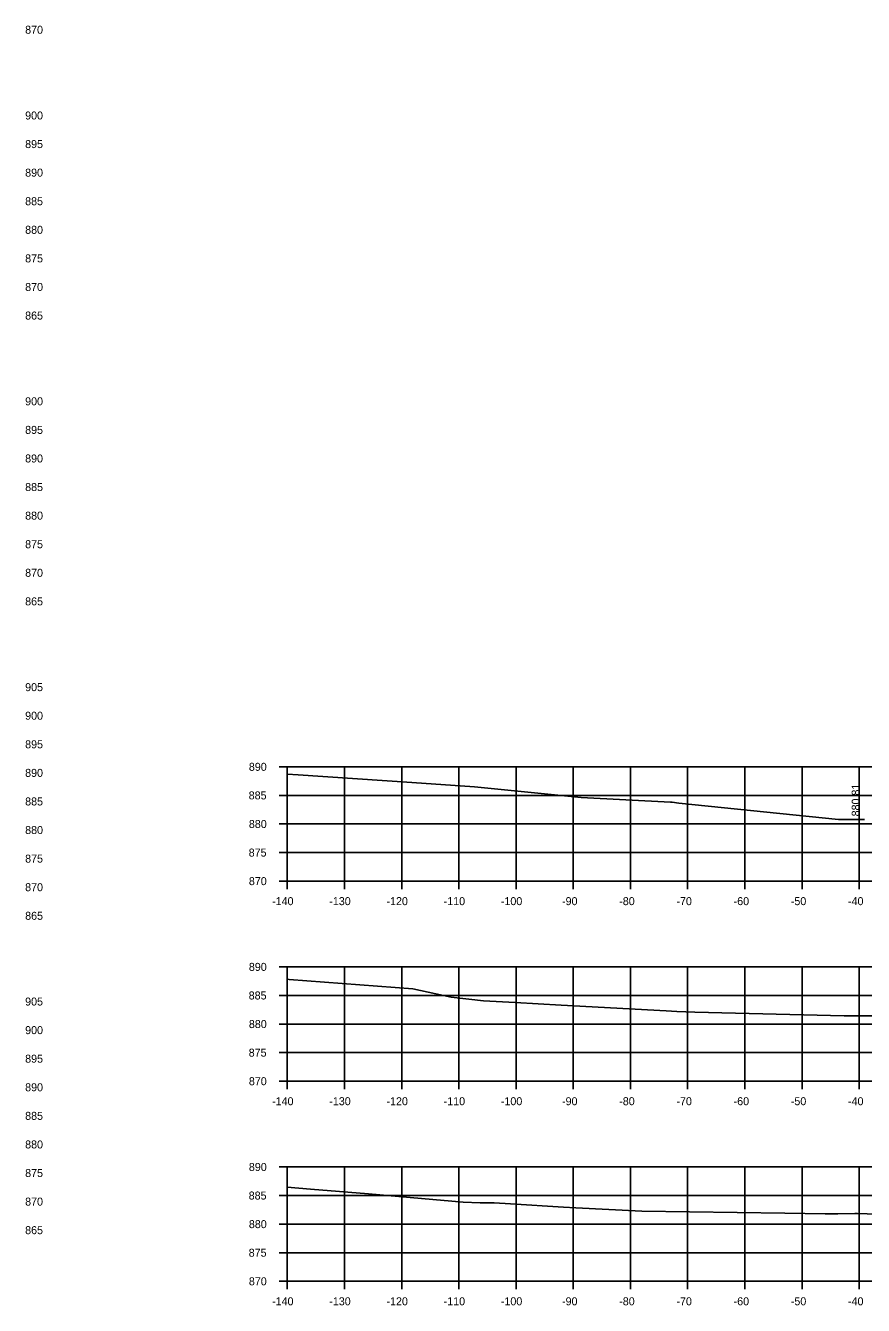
# Model space of a CAD drawing. Extents: x 1098669 to 1198896, y 698679 to 704410.
# Drawn here: x 1112452.1 to 1112598.6, y 701462.1 to 701686 of the extents above; entities that cross this region are included whole.
import ezdxf

# ---------------------------------------------------------------- set-up
doc = ezdxf.new("R2010")
doc.units = 0
for name, color, linetype in [('59', 7, 'Continuous'), ('Proposed Surface', 7, 'Continuous'), ('R_Axis', 7, 'Continuous'), ('R_Axis Annot', 7, 'Continuous'), ('R_Grid', 7, 'Continuous')]:
    doc.layers.add(name, color=color, linetype=linetype)

msp = doc.modelspace()

# ---------------------------------------------------------------- linework, layer by layer
at = {"layer": 'Proposed Surface'}
for points in [[(1112497.82, 701555.06), (1112499.72, 701554.92), (1112519.61, 701553.58), (1112530.55, 701552.84), (1112549.19, 701550.96), (1112564.83, 701550.12), (1112565.09, 701550.11), (1112566.26, 701549.97), (1112594.18, 701547.11), (1112597.47, 701547.11), (1112598.76, 701547.13)], [(1112497.82, 701519.15), (1112498.15, 701519.13), (1112519.79, 701517.47), (1112526.5, 701516), (1112532.12, 701515.4), (1112537.64, 701515.1), (1112545.73, 701514.64), (1112564.06, 701513.62), (1112565.92, 701513.52), (1112569.05, 701513.42), (1112595.2, 701512.74), (1112597.77, 701512.73), (1112600.14, 701512.76)], [(1112497.82, 701482.79), (1112501.88, 701482.44), (1112511.99, 701481.63), (1112528.56, 701480.15), (1112531.52, 701480.04), (1112533.98, 701480.03), (1112536.83, 701479.86), (1112546.1, 701479.31), (1112548.25, 701479.18), (1112559.8, 701478.6), (1112584.8, 701478.21), (1112591.85, 701478.11), (1112592.09, 701478.11), (1112594.1, 701478.14), (1112597.05, 701478.17), (1112597.52, 701478.16), (1112602.56, 701478.01)]]:
    msp.add_lwpolyline(points, dxfattribs=at)
at = {"layer": 'R_Axis'}
for p, q in [((1112496.42, 701556.32), (1112497.82, 701556.32)), ((1112497.82, 701536.32), (1112497.82, 701556.32)), ((1112496.42, 701551.32), (1112497.82, 701551.32)), ((1112496.42, 701546.32), (1112497.82, 701546.32)), ((1112496.42, 701541.32), (1112497.82, 701541.32)), ((1112496.42, 701536.32), (1112497.82, 701536.32)), ((1112497.82, 701536.32), (1112777.82, 701536.32)), ((1112497.82, 701534.92), (1112497.82, 701536.32)), ((1112507.82, 701534.92), (1112507.82, 701536.32)), ((1112517.82, 701534.92), (1112517.82, 701536.32)), ((1112527.82, 701534.92), (1112527.82, 701536.32)), ((1112537.82, 701534.92), (1112537.82, 701536.32)), ((1112547.82, 701534.92), (1112547.82, 701536.32)), ((1112557.82, 701534.92), (1112557.82, 701536.32)), ((1112567.82, 701534.92), (1112567.82, 701536.32)), ((1112577.82, 701534.92), (1112577.82, 701536.32)), ((1112587.82, 701534.92), (1112587.82, 701536.32)), ((1112597.82, 701534.92), (1112597.82, 701536.32)), ((1112496.42, 701521.32), (1112497.82, 701521.32)), ((1112497.82, 701501.32), (1112497.82, 701521.32)), ((1112496.42, 701516.32), (1112497.82, 701516.32)), ((1112496.42, 701511.32), (1112497.82, 701511.32)), ((1112496.42, 701506.32), (1112497.82, 701506.32)), ((1112496.42, 701501.32), (1112497.82, 701501.32)), ((1112497.82, 701501.32), (1112777.82, 701501.32)), ((1112497.82, 701499.92), (1112497.82, 701501.32)), ((1112507.82, 701499.92), (1112507.82, 701501.32)), ((1112517.82, 701499.92), (1112517.82, 701501.32)), ((1112527.82, 701499.92), (1112527.82, 701501.32)), ((1112537.82, 701499.92), (1112537.82, 701501.32)), ((1112547.82, 701499.92), (1112547.82, 701501.32)), ((1112557.82, 701499.92), (1112557.82, 701501.32)), ((1112567.82, 701499.92), (1112567.82, 701501.32)), ((1112577.82, 701499.92), (1112577.82, 701501.32)), ((1112587.82, 701499.92), (1112587.82, 701501.32)), ((1112597.82, 701499.92), (1112597.82, 701501.32)), ((1112496.42, 701486.32), (1112497.82, 701486.32)), ((1112497.82, 701466.32), (1112497.82, 701486.32)), ((1112496.42, 701481.32), (1112497.82, 701481.32)), ((1112496.42, 701476.32), (1112497.82, 701476.32)), ((1112496.42, 701471.32), (1112497.82, 701471.32)), ((1112496.42, 701466.32), (1112497.82, 701466.32)), ((1112497.82, 701466.32), (1112777.82, 701466.32)), ((1112497.82, 701464.92), (1112497.82, 701466.32)), ((1112507.82, 701464.92), (1112507.82, 701466.32)), ((1112517.82, 701464.92), (1112517.82, 701466.32)), ((1112527.82, 701464.92), (1112527.82, 701466.32)), ((1112537.82, 701464.92), (1112537.82, 701466.32)), ((1112547.82, 701464.92), (1112547.82, 701466.32)), ((1112557.82, 701464.92), (1112557.82, 701466.32)), ((1112567.82, 701464.92), (1112567.82, 701466.32)), ((1112577.82, 701464.92), (1112577.82, 701466.32)), ((1112587.82, 701464.92), (1112587.82, 701466.32)), ((1112597.82, 701464.92), (1112597.82, 701466.32))]:
    msp.add_line(p, q, dxfattribs=at)
at = {"layer": 'R_Grid'}
for p, q in [((1112497.82, 701556.32), (1112777.82, 701556.32)), ((1112497.82, 701536.32), (1112497.82, 701556.32)), ((1112507.82, 701536.32), (1112507.82, 701556.32)), ((1112517.82, 701536.32), (1112517.82, 701556.32)), ((1112527.82, 701536.32), (1112527.82, 701556.32)), ((1112537.82, 701536.32), (1112537.82, 701556.32)), ((1112547.82, 701536.32), (1112547.82, 701556.32)), ((1112557.82, 701536.32), (1112557.82, 701556.32)), ((1112567.82, 701536.32), (1112567.82, 701556.32)), ((1112577.82, 701536.32), (1112577.82, 701556.32)), ((1112587.82, 701536.32), (1112587.82, 701556.32)), ((1112597.82, 701536.32), (1112597.82, 701556.32)), ((1112497.82, 701551.32), (1112777.82, 701551.32)), ((1112497.82, 701546.32), (1112777.82, 701546.32)), ((1112497.82, 701541.32), (1112777.82, 701541.32)), ((1112497.82, 701536.32), (1112777.82, 701536.32)), ((1112497.82, 701521.32), (1112777.82, 701521.32)), ((1112497.82, 701501.32), (1112497.82, 701521.32)), ((1112507.82, 701501.32), (1112507.82, 701521.32)), ((1112517.82, 701501.32), (1112517.82, 701521.32)), ((1112527.82, 701501.32), (1112527.82, 701521.32)), ((1112537.82, 701501.32), (1112537.82, 701521.32)), ((1112547.82, 701501.32), (1112547.82, 701521.32)), ((1112557.82, 701501.32), (1112557.82, 701521.32)), ((1112567.82, 701501.32), (1112567.82, 701521.32)), ((1112577.82, 701501.32), (1112577.82, 701521.32)), ((1112587.82, 701501.32), (1112587.82, 701521.32)), ((1112597.82, 701501.32), (1112597.82, 701521.32)), ((1112497.82, 701516.32), (1112777.82, 701516.32)), ((1112497.82, 701511.32), (1112777.82, 701511.32)), ((1112497.82, 701506.32), (1112777.82, 701506.32)), ((1112497.82, 701501.32), (1112777.82, 701501.32)), ((1112497.82, 701486.32), (1112777.82, 701486.32)), ((1112497.82, 701466.32), (1112497.82, 701486.32)), ((1112507.82, 701466.32), (1112507.82, 701486.32)), ((1112517.82, 701466.32), (1112517.82, 701486.32)), ((1112527.82, 701466.32), (1112527.82, 701486.32)), ((1112537.82, 701466.32), (1112537.82, 701486.32)), ((1112547.82, 701466.32), (1112547.82, 701486.32)), ((1112557.82, 701466.32), (1112557.82, 701486.32)), ((1112567.82, 701466.32), (1112567.82, 701486.32)), ((1112577.82, 701466.32), (1112577.82, 701486.32)), ((1112587.82, 701466.32), (1112587.82, 701486.32)), ((1112597.82, 701466.32), (1112597.82, 701486.32)), ((1112497.82, 701481.32), (1112777.82, 701481.32)), ((1112497.82, 701476.32), (1112777.82, 701476.32)), ((1112497.82, 701471.32), (1112777.82, 701471.32)), ((1112497.82, 701466.32), (1112777.82, 701466.32))]:
    msp.add_line(p, q, dxfattribs=at)

# ---------------------------------------------------------------- texts
at = {"layer": '59'}
msp.add_text(' 880.81', height=1.4, rotation=90, dxfattribs=at).set_placement((1112597.91, 701547.13))
at = {"layer": 'R_Axis Annot'}
for s, p in [('870', (1112451.98, 701684.56)), ('900', (1112451.98, 701669.56)), ('895', (1112451.98, 701664.56)), ('890', (1112451.98, 701659.56)), ('885', (1112451.98, 701654.56)), ('880', (1112451.98, 701649.56)), ('875', (1112451.98, 701644.56)), ('870', (1112451.98, 701639.56)), ('865', (1112451.98, 701634.56)), ('900', (1112451.98, 701619.56)), ('895', (1112451.98, 701614.56)), ('890', (1112451.98, 701609.56)), ('885', (1112451.98, 701604.56)), ('880', (1112451.98, 701599.56)), ('875', (1112451.98, 701594.56)), ('870', (1112451.98, 701589.56)), ('865', (1112451.98, 701584.56)), ('905', (1112451.98, 701569.56)), ('900', (1112451.98, 701564.56)), ('895', (1112451.98, 701559.56)), ('890', (1112451.98, 701554.56)), ('890', (1112491.1, 701555.62)), ('885', (1112491.07, 701550.62)), ('885', (1112451.98, 701549.56)), ('880', (1112491.1, 701545.62)), ('880', (1112451.98, 701544.56)), ('875', (1112451.98, 701539.56)), ('875', (1112491.07, 701540.62)), ('870', (1112451.98, 701534.56)), ('870', (1112491.1, 701535.62)), ('-140', (1112495.16, 701532.12)), ('-130', (1112505.16, 701532.12)), ('-120', (1112515.16, 701532.12)), ('-110', (1112525.16, 701532.12)), ('-100', (1112535.16, 701532.12)), ('-90', (1112545.86, 701532.12)), ('-80', (1112555.86, 701532.12)), ('-70', (1112565.86, 701532.12)), ('-60', (1112575.86, 701532.12)), ('-50', (1112585.86, 701532.12)), ('-40', (1112595.86, 701532.12)), ('865', (1112451.98, 701529.56)), ('890', (1112491.1, 701520.62)), ('905', (1112451.98, 701514.56)), ('885', (1112491.07, 701515.62)), ('900', (1112451.98, 701509.56)), ('880', (1112491.1, 701510.62)), ('875', (1112491.07, 701505.62)), ('895', (1112451.98, 701504.56)), ('870', (1112491.1, 701500.62)), ('890', (1112451.98, 701499.56)), ('-140', (1112495.16, 701497.12)), ('-130', (1112505.16, 701497.12)), ('-120', (1112515.16, 701497.12)), ('-110', (1112525.16, 701497.12)), ('-100', (1112535.16, 701497.12)), ('-90', (1112545.86, 701497.12)), ('-80', (1112555.86, 701497.12)), ('-70', (1112565.86, 701497.12)), ('-60', (1112575.86, 701497.12)), ('-50', (1112585.86, 701497.12)), ('-40', (1112595.86, 701497.12)), ('885', (1112451.98, 701494.56)), ('880', (1112451.98, 701489.56)), ('890', (1112491.1, 701485.62)), ('875', (1112451.98, 701484.56)), ('885', (1112491.07, 701480.62)), ('870', (1112451.98, 701479.56)), ('865', (1112451.98, 701474.56)), ('880', (1112491.1, 701475.62)), ('875', (1112491.07, 701470.62)), ('870', (1112491.1, 701465.62)), ('-140', (1112495.16, 701462.12)), ('-130', (1112505.16, 701462.12)), ('-120', (1112515.16, 701462.12)), ('-110', (1112525.16, 701462.12)), ('-100', (1112535.16, 701462.12)), ('-90', (1112545.86, 701462.12)), ('-80', (1112555.86, 701462.12)), ('-70', (1112565.86, 701462.12)), ('-60', (1112575.86, 701462.12)), ('-50', (1112585.86, 701462.12)), ('-40', (1112595.86, 701462.12))]:
    msp.add_text(s, height=1.4, dxfattribs=at).set_placement(p)

doc.saveas('drawing.dxf')
